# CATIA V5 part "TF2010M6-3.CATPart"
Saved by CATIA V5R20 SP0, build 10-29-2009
Part number: TF2010M6-3
Revision: ANY
Definition: UNKNOWN
Nomenclature: TF2010M6-3
Source: Unknown
Bounding box of the stored display mesh (mm): x -4.85 to 4.85, y 0 to 4.05, z -4.85 to 4.85
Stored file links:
  C:\Users\Utente\Desktop\IO LAVORO\3D X SITO CF\CUMSA\3D files RCM\RCM 204810\TF2010M6-3.CATPart
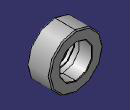
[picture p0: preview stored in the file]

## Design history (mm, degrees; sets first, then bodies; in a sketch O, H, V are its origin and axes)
Body1 "Cortar-Revolución1" (main body)
  Solid1: solid without history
